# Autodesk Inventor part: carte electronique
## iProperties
Author: Administrateur
Created: 2001-04
Part Number: carte electronique
Material: Par défaut
Document SubType Name: Modélisation
Designer: Administrateur
Control State: 0
Master: False
Checked Out: False
PropertySet Name: Design Tracking Control
Shininess: 20.0
PropertySet Name: _Private Model Information
Length Units: 11269
Angle Units: 11283
Time Units: 11279
Mass Units: 11290
Length Display Precision: 3
Angle Display Precision: 2
Compacted: False
Density: 0.0
Volumn: 0.0
Area: 0.0
PropertySet Name: Model Information
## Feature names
1. Extrusion5
